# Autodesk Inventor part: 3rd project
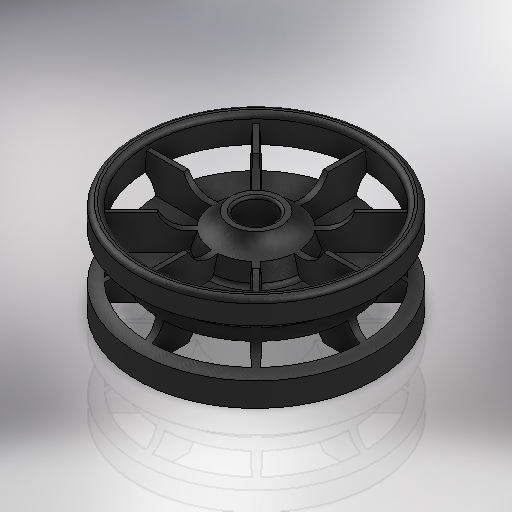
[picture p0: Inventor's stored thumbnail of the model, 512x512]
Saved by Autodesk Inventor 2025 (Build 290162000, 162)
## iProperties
Created: 2024-06
Part Number: 3rd project
Material: Generic
Document SubType Name: Modeling
Designer: aryan
Density: 1 g/cm^3
Appearance: Diamond plate - Dark Gray
Author: aryan
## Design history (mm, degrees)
sketch "Sketch1"
  geometry: L1 (0, 13.477)-(0, 0); L2 (0, 0)-(-20.452, 0); L3 (-9.525, 0)-(-9.525, 20.764); L4 (-9.525, 20.764)-(-19.685, 20.764); L5 (-19.685, 20.764)-(-25.4, 3.175); L6 (-25.4, 3.175)-(-57.15, 3.175); L7 (-57.15, 3.175)-(-57.15, 25.4); L8 (-57.15, 25.4)-(-63.5, 25.4); L9 (-63.5, 25.4)-(-63.5, -2.978); L10 (-9.525, 0)-(-9.525, -20.764); L11 (-9.525, -20.764)-(-19.685, -20.764); L12 (-19.685, -20.764)-(-25.4, -3.175); L13 (-25.4, -3.175)-(-57.15, -3.175); L14 (-57.15, -3.175)-(-57.15, -25.4); L15 (-57.15, -25.4)-(-63.5, -25.4); L16 (-63.5, -25.4)-(-63.5, -2.978); 6 further points
  constraints: 32 end point, 6 midpoint, 6 perpendicular, 6 symmetric about line, 1 parallel, 1 point on line, 1 vertical
  dimensions: "d0" = 10.16 distance of L3.end L4.end; "d1" = 6.35 distance of L7.end L8.end; "d2" = 19.05 diameter of point (-9.525, 10.382) L1; "d3" = 6.35 distance of point (-41.275, -3.175) point (-41.275, 3.175); "d4" = 50.8 distance of point (-60.325, -25.4) point (-60.325, 25.4); "d5" = 18 deg angle of L3 L5; "d6" = 50.8 diameter of L5.end L1; "d7" = 127 diameter of point (-63.5, 11.211) L1
revolve "Revolution1" sketch "Sketch1" stored, may be unused: angle "d8" = 90 deg
fillet "Fillet1" dims "d9" = 2.54
fillet "Fillet2" dims "d10" = 1.27
sketch "Sketch2"
  geometry: L1 (-27.245, 0)-(-54.61, 0); 3 further points
  constraints: 2 end point, 2 horizontal alignment, 1 horizontal, 2 other
feature "Rib1" sketch "Sketch2" dims "d11" = 2.54, "d12" = 2.54, "d13" = 3 deg, "d14" = 0, "d15" = 2.54, "d16" = 2.54
mirror "Mirror1"
pattern_circular "Circular Pattern1" dims "d18" = 360 deg
sketch "Sketch3"
  geometry: L1 (0, 0)-(41.876, 0); L2 (22.86, 63.5)-(-25.4, 63.5) reference; L3 (25.4, -59.69)-(25.4, 59.69) reference; L4 (-25.4, 57.15)-(-25.4, -57.15) reference; C1 r 12.7 at (0, 63.5); C2 r 12.7 at (25.4, 25.394); C3 r 12.7 at (-25.4, 25.394)
  constraints: 3 centre point, 3 point on line, 2 end point, 1 horizontal
  dimensions: "d20" = 25.4 diameter of C1; "d21" = 25.4 diameter of C2; "d22" = 25.4 diameter of C3
revolve "Revolution2" sketch "Sketch3" stored, may be unused: angle "d23" = 90 deg
body "Solid1"
